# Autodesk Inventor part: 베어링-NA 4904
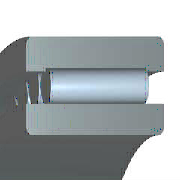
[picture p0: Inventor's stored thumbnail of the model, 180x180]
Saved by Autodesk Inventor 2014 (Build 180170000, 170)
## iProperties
IsCustomPart: 1
Company: 한국ATC센터
Created: 2009-02
Part Number: 베어링-NA 4904
Material: 강철, 연강
Description: 니들 롤러 베어링 - 경계 치수 및 공차
Document SubType Name: Modeling
Standard: KS B 2029
Designer: KYOUNG IL JANG
Standards Organization: KS
Language: ko-KR
Size Designation: NA 4904 - 20 x 37 x 17
Categories: <MemberInstance><Categories><Category DisplayName="샤프트 부품" InternalName="7f7aeb1f-a693-4053-b835-cee3144e0d98" Mnemonic="SHFT"><Category DisplayName="베어링" Inter
Density: 7.86 g/cm^3
Mass: 73.0306 g
Surface Area: 90.2463 cm^2
Volume: 9.29143 cm^3
Vendor: CBT Solutions
Appearance: 강철
Author: KYOUNG IL JANG
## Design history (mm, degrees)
sketch "스케치"
  geometry: L1 (2.429, 16)-(14.571, 16); L2 (14.571, 16)-(14.571, 12.5); L3 (17, 12.5)-(0, 12.5); L4 (2.429, 12.5)-(2.429, 16); L5 (2.429, 14.25)-(14.571, 14.25); L6 (8.5, 14.25)-(8.5, 12.5); L7 (0, 10)-(17, 10); L8 (0, 18.5)-(17, 18.5); L9 (17, 10)-(17, 12.5); L10 (17, 15.65)-(17, 18.5); L11 (2.429, 15.65)-(0, 15.65); L12 (14.571, 15.65)-(17, 15.65); L13 (-6, 0)-(36, 0) reference; L14 (0, -1.9)-(0, 14.9) reference
  constraints: 24 end point, 8 point on line, 3 midpoint, 3 parallel, 3 perpendicular, 2 symmetric about line, 1 horizontal, 1 other
  dimensions: "d6" = 20 diameter of L7 L13 (= WD); "d7" = 25 diameter of L3 L13 (= KID1); "d8" = 37 diameter of L8 L13 (= BD); "d9" = 28.5 diameter of L6.start L13 (= 0.5 x WD + 0.5 x BD); "d10" = 31.3 diameter of L12 L13 (= 0.9 x BD + 0.9 x WD - 0.8 x KID1); "d11" = 32 diameter of L1 L13 (= BD + WD - KID1); "d12" = 2.42857 distance between parallel lines of L14 L4 (= 0.142857 x KB); "d13" = 17 distance between parallel lines of L14 L9 (= KB); "d14" = 14.57143 distance between parallel lines of L14 L2 (= 0.857143 x KB)
revolve "본체" stored, may be unused: angle "d17" = 90 deg
revolve "롤러" stored, may be unused: angle "d18" = 90 deg
pattern_circular "IDS_ARRAYROLLER[SIMPL:T]" dims angle "d2" = 360 deg
body "Solid1"
fillet "모깎기1" dims "d0" = 0.3 (= KRS)
other parameters: "WD" = 20 [user parameter; used in 6 equation terms], "BD" = 37 [user parameter; used in 6 equation terms], "KB" = 17 [user parameter; used in 3 equation terms], "KID1" = 25 [user parameter; used in 4 equation terms], "KRS" = 0.3 [user parameter; used in 1 equation term], "d3" = 0, "d4" = 0, "d5" = 0, "d15" = 0, "d16" = 0, "BC0" = 2.36e+07 [user parameter], "BBA" = 0 [user parameter], "BC" = 1.9e+07 [user parameter], "BR" = 18.5 (= 0.5 x BD) [user parameter]
